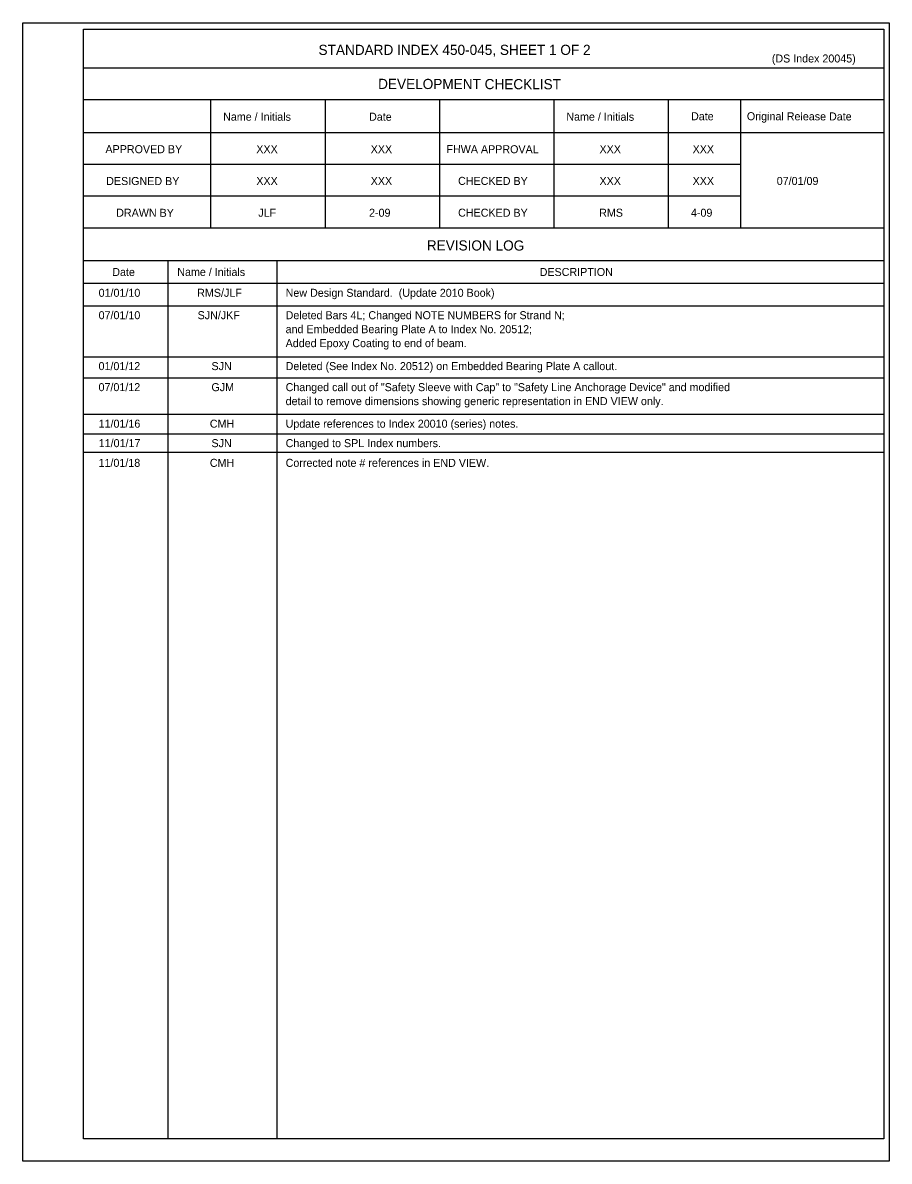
# Model space of a CAD drawing. Extents: x -21.7 to 40.7, y -0.2 to 17.4.
# Drawn here: x 29.79 to 40.7, y 2.25 to 16.59 of the extents above; entities that cross this region are included whole.
import ezdxf

# ---------------------------------------------------------------- set-up
doc = ezdxf.new("R2010")
doc.units = 0
for name, color, linetype in [('AdhocPoint_dp', 7, 'Continuous'), ('Border', 7, 'Continuous'), ('PlotBorder_dp', 7, 'Continuous'), ('TextStructures', 7, 'Continuous')]:
    doc.layers.add(name, color=color, linetype=linetype)

msp = doc.modelspace()

# ---------------------------------------------------------------- linework, layer by layer
at = {"layer": 'AdhocPoint_dp'}
for p, q in [((30.559, 13.024), (40.633, 13.024)), ((30.559, 12.383), (40.633, 12.383)), ((30.559, 12.118), (40.633, 12.118)), ((30.559, 11.658), (40.633, 11.658)), ((30.559, 11.413), (40.633, 11.413)), ((30.559, 11.18), (40.633, 11.18))]:
    msp.add_line(p, q, dxfattribs=at)
at = {"layer": 'Border'}
for p, q in [((40.633, 16.015), (30.559, 16.015)), ((40.633, 15.615), (30.559, 15.615)), ((32.159, 15.615), (32.159, 14.002)), ((33.599, 15.615), (33.599, 14.002)), ((35.039, 15.615), (35.039, 14.002)), ((36.479, 15.615), (36.479, 14.002)), ((37.919, 15.615), (37.919, 14.002)), ((38.827, 15.615), (38.827, 14.002)), ((40.633, 15.202), (30.559, 15.202)), ((38.827, 14.802), (30.559, 14.802)), ((38.827, 14.402), (30.559, 14.402)), ((40.633, 14.002), (30.559, 14.002)), ((40.633, 13.588), (30.559, 13.588)), ((31.62, 13.588), (31.62, 2.534)), ((32.991, 13.588), (32.991, 2.534)), ((40.633, 13.306), (30.559, 13.306))]:
    msp.add_line(p, q, dxfattribs=at)
msp.add_lwpolyline([(30.56, 16.506), (40.633, 16.506), (40.633, 2.534), (30.56, 2.534)], close=True, dxfattribs=at)
at = {"layer": 'PlotBorder_dp'}
msp.add_line((29.794, 2.254), (29.794, 2.254), dxfattribs=at)
msp.add_lwpolyline([(29.794, 16.587), (40.701, 16.587), (40.701, 2.254), (29.794, 2.254)], close=True, dxfattribs=at)

# ---------------------------------------------------------------- texts
at = {"layer": 'TextStructures'}
for s, height, p in [('STANDARD INDEX 450-045, SHEET 1 OF 2', 0.128, (33.517, 16.182)), ('(DS Index 20045)', 0.1008, (39.223, 16.087)), ('XXX', 0.1008, (32.734, 14.945)), ('XXX', 0.1008, (34.174, 14.945)), ('XXX', 0.1008, (37.054, 14.945)), ('XXX', 0.1008, (38.226, 14.945)), ('XXX', 0.1008, (32.734, 14.545)), ('XXX', 0.1008, (34.174, 14.545)), ('XXX', 0.1008, (37.054, 14.545)), ('XXX', 0.1008, (38.226, 14.545)), ('07/01/09', 0.1008, (39.285, 14.545)), ('JLF', 0.1008, (32.759, 14.145)), ('2-09', 0.1008, (34.153, 14.145)), ('RMS', 0.1008, (37.05, 14.145)), ('4-09', 0.1008, (38.205, 14.145)), ('DESCRIPTION', 0.1008, (36.301, 13.399)), ('01/01/10', 0.1008, (30.749, 13.137)), ('RMS/JLF', 0.1008, (31.99, 13.137)), ('New Design Standard.  (Update 2010 Book)', 0.1008, (33.103, 13.137)), ('07/01/10', 0.1008, (30.749, 12.855)), ('SJN/JKF', 0.1008, (31.995, 12.855)), ('Deleted Bars 4L; Changed NOTE NUMBERS for Strand N;', 0.1008, (33.103, 12.855)), ('and Embedded Bearing Plate A to Index No. 20512;', 0.1008, (33.103, 12.679)), ('Added Epoxy Coating to end of beam.', 0.1008, (33.103, 12.503)), ('01/01/12', 0.1008, (30.748, 12.214)), ('SJN', 0.1008, (32.17, 12.214)), ('Deleted (See Index No. 20512) on Embedded Bearing Plate A callout.', 0.1008, (33.103, 12.214)), ('07/01/12', 0.1008, (30.748, 11.949)), ('GJM', 0.1008, (32.169, 11.949)), ('Changed call out of "Safety Sleeve with Cap" to "Safety Line Anchorage Device" and modified', 0.1008, (33.103, 11.949)), ('detail to remove dimensions showing generic representation in END VIEW only.', 0.1008, (33.103, 11.773)), ('11/01/16', 0.1008, (30.749, 11.489)), ('CMH', 0.1008, (32.149, 11.489)), ('Update references to Index 20010 (series) notes.', 0.1008, (33.103, 11.489)), ('11/01/17', 0.1008, (30.75, 11.244)), ('SJN', 0.1008, (32.17, 11.244)), ('Changed to SPL Index numbers.', 0.1008, (33.103, 11.244)), ('11/01/18', 0.1008, (30.748, 10.996)), ('CMH', 0.1008, (32.149, 10.996)), ('Corrected note # references in END VIEW.', 0.1008, (33.103, 10.996))]:
    msp.add_text(s, height=height, dxfattribs=at).set_placement(p)
for s, height, p in [('DEVELOPMENT CHECKLIST', 0.128, (34.267, 15.754)), ('Name / Initials', 0.1008, (32.316, 15.355)), ('Date', 0.1008, (34.153, 15.354)), ('Name / Initials', 0.1008, (36.636, 15.355)), ('Date', 0.1008, (38.206, 15.36)), ('Original Release Date', 0.1008, (38.909, 15.36)), ('APPROVED BY', 0.1008, (30.835, 14.946)), ('FHWA APPROVAL', 0.1008, (35.127, 14.946)), ('DESIGNED BY', 0.1008, (30.844, 14.545)), ('CHECKED BY', 0.1008, (35.274, 14.546)), ('DRAWN BY', 0.1008, (30.97, 14.145)), ('CHECKED BY', 0.1008, (35.274, 14.146)), ('REVISION LOG', 0.128, (34.88, 13.721)), ('Date', 0.1008, (30.921, 13.399)), ('Name / Initials', 0.1008, (31.739, 13.4))]:
    msp.add_text(s, height=height, rotation=359.8756, dxfattribs=at).set_placement(p)

doc.saveas('drawing.dxf')
